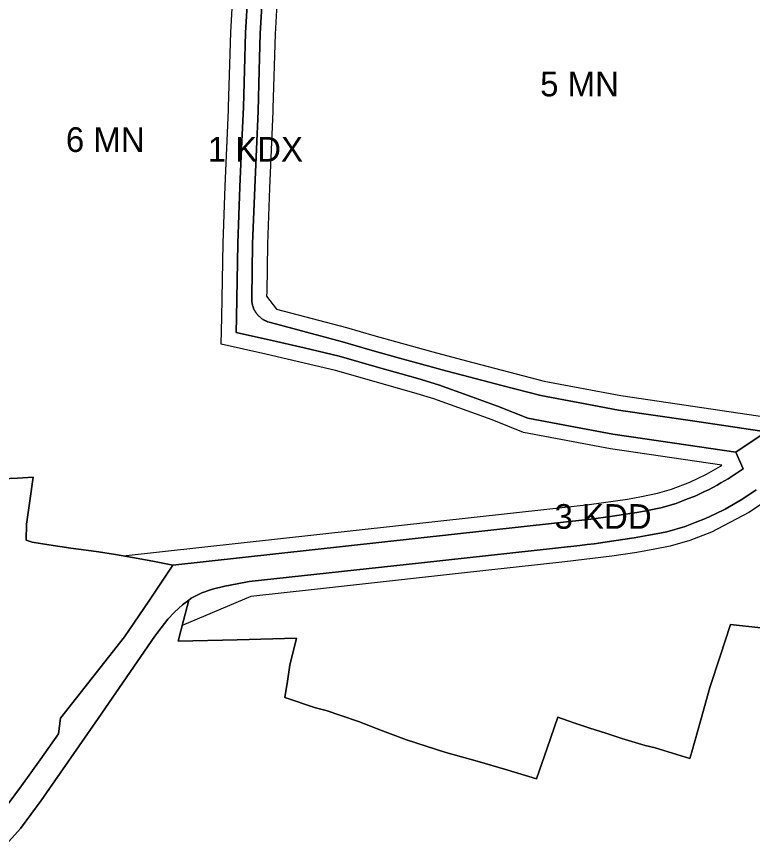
# Model space of a CAD drawing. Extents: x 7423432 to 7425824, y 5537848 to 5539677.
# Drawn here: x 7423719.6 to 7424018.1, y 5538438.2 to 5538772.8 of the extents above; entities that cross this region are included whole.
import ezdxf

# ---------------------------------------------------------------- set-up
doc = ezdxf.new("R2010")
doc.units = 0
for name, color, linetype in [('linie_rozgraniczajace', 7, 'Continuous'), ('linie_zabudowy_nieprzekraczalne', 7, 'Continuous'), ('oznaczenia_przeznaczen', 7, 'Continuous')]:
    doc.layers.add(name, color=color, linetype=linetype)

msp = doc.modelspace()

# ---------------------------------------------------------------- linework, layer by layer
at = {"layer": 'linie_rozgraniczajace'}
for points in [[(7423719.48, 5538874.86), (7423719.65, 5538874.75), (7423719.82, 5538874.64), (7423720, 5538874.54), (7423720.17, 5538874.44), (7423720.24, 5538874.4), (7423720.99, 5538874.02), (7423732.84, 5538868.82), (7423744.7, 5538863.63), (7423755.6, 5538859.21), (7423766.51, 5538854.8), (7423776.03, 5538851.5), (7423785.56, 5538848.2), (7423796.06, 5538844.9), (7423803.49, 5538842.6), (7423810.92, 5538840.3), (7423822.63, 5538838.5), (7423822.16, 5538830.31), (7423821.7, 5538822.11), (7423821.01, 5538809.88), (7423820.31, 5538797.65), (7423819.39, 5538781.73), (7423818.46, 5538765.81), (7423818.02, 5538750.81)], [(7423813.4, 5538782.03), (7423812.47, 5538766.07), (7423812.03, 5538751.03), (7423811.58, 5538735.98), (7423810.87, 5538719.18), (7423810.21, 5538703.69), (7423809.78, 5538692.21), (7423809.35, 5538680.73), (7423809.08, 5538665.72), (7423808.82, 5538650.7), (7423808.67, 5538644.66), (7423815.33, 5538643.18), (7423821.99, 5538641.71), (7423836.24, 5538638.37), (7423850.48, 5538635.03), (7423866.43, 5538630.49), (7423882.38, 5538625.95), (7423890.74, 5538623.35), (7423902.7, 5538619.07), (7423914.65, 5538614.79), (7423926.89, 5538609.87)], [(7423808.67, 5538644.66), (7423808.82, 5538650.7), (7423809.08, 5538665.72), (7423809.35, 5538680.73), (7423809.78, 5538692.21), (7423810.21, 5538703.69), (7423810.87, 5538719.18), (7423811.58, 5538735.98), (7423812.03, 5538751.03), (7423812.47, 5538766.07), (7423813.4, 5538782.03)], [(7423818.21, 5538650.91), (7423818.07, 5538651.05), (7423817.93, 5538651.18), (7423817.79, 5538651.32), (7423817.65, 5538651.46), (7423817.52, 5538651.61), (7423817.38, 5538651.75), (7423817.26, 5538651.9), (7423817.13, 5538652.06), (7423817.01, 5538652.21), (7423816.89, 5538652.37), (7423816.78, 5538652.53), (7423816.66, 5538652.69), (7423816.56, 5538652.85), (7423816.45, 5538653.02), (7423816.35, 5538653.19), (7423816.25, 5538653.36), (7423816.15, 5538653.53), (7423816.06, 5538653.71), (7423815.97, 5538653.88), (7423815.89, 5538654.06), (7423815.81, 5538654.24), (7423815.73, 5538654.42), (7423815.66, 5538654.6), (7423815.59, 5538654.79), (7423815.52, 5538654.97), (7423815.46, 5538655.16), (7423815.4, 5538655.35), (7423815.35, 5538655.54), (7423815.3, 5538655.73), (7423815.25, 5538655.92), (7423815.21, 5538656.11), (7423815.17, 5538656.3), (7423815.13, 5538656.5), (7423815.1, 5538656.69), (7423815.08, 5538656.89), (7423815.05, 5538657.08), (7423815.03, 5538657.28), (7423815.02, 5538657.47), (7423815.01, 5538657.67), (7423815, 5538657.87), (7423815, 5538658.06), (7423815, 5538658.26), (7423815, 5538658.46), (7423815.01, 5538658.65), (7423815.18, 5538669.61), (7423815.35, 5538680.57), (7423816.21, 5538703.45), (7423816.87, 5538718.94), (7423817.53, 5538734.42), (7423818.02, 5538750.81), (7423818.46, 5538765.81), (7423819.39, 5538781.73)], [(7423818.02, 5538750.81), (7423817.53, 5538734.42), (7423816.87, 5538718.94), (7423816.21, 5538703.45), (7423815.35, 5538680.57), (7423815.18, 5538669.61), (7423815.01, 5538658.65), (7423815, 5538658.46), (7423815, 5538658.26), (7423815, 5538658.06), (7423815, 5538657.87), (7423815.01, 5538657.67), (7423815.02, 5538657.47), (7423815.03, 5538657.28), (7423815.05, 5538657.08), (7423815.08, 5538656.89), (7423815.1, 5538656.69), (7423815.13, 5538656.5), (7423815.17, 5538656.3), (7423815.21, 5538656.11), (7423815.25, 5538655.92), (7423815.3, 5538655.73), (7423815.35, 5538655.54), (7423815.4, 5538655.35), (7423815.46, 5538655.16), (7423815.52, 5538654.97), (7423815.59, 5538654.79), (7423815.66, 5538654.6), (7423815.73, 5538654.42), (7423815.81, 5538654.24), (7423815.89, 5538654.06), (7423815.97, 5538653.88), (7423816.06, 5538653.71), (7423816.15, 5538653.53), (7423816.25, 5538653.36), (7423816.35, 5538653.19), (7423816.45, 5538653.02), (7423816.56, 5538652.85), (7423816.66, 5538652.69), (7423816.78, 5538652.53), (7423816.89, 5538652.37), (7423817.01, 5538652.21), (7423817.13, 5538652.06), (7423817.26, 5538651.9), (7423817.38, 5538651.75), (7423817.52, 5538651.61), (7423817.65, 5538651.46), (7423817.79, 5538651.32), (7423817.93, 5538651.18), (7423818.07, 5538651.05), (7423818.21, 5538650.91), (7423818.36, 5538650.78), (7423818.51, 5538650.66), (7423818.66, 5538650.53), (7423818.82, 5538650.41), (7423818.98, 5538650.3), (7423819.14, 5538650.18), (7423819.3, 5538650.07), (7423819.47, 5538649.96), (7423819.63, 5538649.86), (7423819.8, 5538649.76), (7423819.97, 5538649.66), (7423820.15, 5538649.57), (7423820.32, 5538649.48), (7423820.5, 5538649.39), (7423820.68, 5538649.3), (7423820.86, 5538649.23), (7423821.04, 5538649.15), (7423821.22, 5538649.08), (7423821.4, 5538649.01), (7423821.57, 5538648.95), (7423822.59, 5538648.65), (7423837.22, 5538644.76), (7423851.85, 5538640.87), (7423862.87, 5538637.61), (7423874.84, 5538634.28), (7423886.82, 5538630.96), (7423893.65, 5538629.12), (7423900.48, 5538627.29), (7423916.36, 5538623.16), (7423932.25, 5538619.04), (7423947.99, 5538616.1), (7423963.72, 5538613.17), (7423993.67, 5538608.75), (7424023.61, 5538604.33), (7424011.34, 5538596.04), (7423986.4, 5538599.72), (7423961.45, 5538603.39), (7423944.17, 5538606.63), (7423926.89, 5538609.87), (7423914.65, 5538614.79), (7423902.7, 5538619.07), (7423890.74, 5538623.35), (7423882.38, 5538625.95), (7423866.43, 5538630.49), (7423850.48, 5538635.03), (7423836.24, 5538638.37), (7423821.99, 5538641.71), (7423815.33, 5538643.18), (7423808.67, 5538644.66)], [(7424023.61, 5538604.33), (7423993.67, 5538608.75), (7423963.72, 5538613.17), (7423947.99, 5538616.1), (7423932.25, 5538619.04), (7423916.36, 5538623.16), (7423900.48, 5538627.29), (7423893.65, 5538629.12), (7423886.82, 5538630.96), (7423874.84, 5538634.28), (7423862.87, 5538637.61), (7423851.85, 5538640.87), (7423837.22, 5538644.76), (7423822.59, 5538648.65), (7423821.57, 5538648.95), (7423821.4, 5538649.01), (7423821.22, 5538649.08), (7423821.04, 5538649.15), (7423820.86, 5538649.23), (7423820.68, 5538649.3), (7423820.5, 5538649.39), (7423820.32, 5538649.48), (7423820.15, 5538649.57), (7423819.97, 5538649.66), (7423819.8, 5538649.76), (7423819.63, 5538649.86), (7423819.47, 5538649.96), (7423819.3, 5538650.07), (7423819.14, 5538650.18), (7423818.98, 5538650.3), (7423818.82, 5538650.41), (7423818.66, 5538650.53), (7423818.51, 5538650.66), (7423818.36, 5538650.78), (7423818.21, 5538650.91)], [(7423926.89, 5538609.87), (7423944.17, 5538606.63), (7423961.45, 5538603.39), (7423986.4, 5538599.72), (7424011.34, 5538596.04), (7424014.31, 5538589.31), (7424008.21, 5538585.35), (7424005.23, 5538583.61), (7424003.7, 5538582.71), (7424002.26, 5538581.87), (7424000.17, 5538580.85), (7423998.64, 5538580.11), (7423995.01, 5538578.36), (7423991.07, 5538576.84), (7423987.13, 5538575.33), (7423980.93, 5538573.59), (7423974.11, 5538572.23), (7423971.21, 5538571.7), (7423968.31, 5538571.17), (7423960.41, 5538570.02), (7423952.52, 5538568.87), (7423867.75, 5538559.56), (7423782.99, 5538550.25), (7423774.84, 5538551.85), (7423766.69, 5538553.44), (7423759.79, 5538554.57), (7423752.89, 5538555.7), (7423747.79, 5538556.32), (7423741.65, 5538557.21), (7423732.65, 5538558.59), (7423725.99, 5538559.67), (7423723.52, 5538560.35), (7423723.71, 5538566.88), (7423725.01, 5538576.42), (7423726.32, 5538585.95), (7423720.05, 5538585.62), (7423713.79, 5538585.28)], [(7423713.46, 5538449.88), (7423721.65, 5538460.83), (7423729.13, 5538471.33), (7423736.62, 5538481.83), (7423737.03, 5538485.04), (7423737.45, 5538488.25), (7423750.45, 5538504.71), (7423763.45, 5538521.17), (7423773.22, 5538535.71), (7423782.99, 5538550.25), (7423867.75, 5538559.56), (7423952.52, 5538568.87), (7423960.41, 5538570.02), (7423968.31, 5538571.17), (7423971.21, 5538571.7), (7423974.11, 5538572.23), (7423980.93, 5538573.59), (7423987.13, 5538575.33), (7423991.07, 5538576.84), (7423995.01, 5538578.36), (7423998.64, 5538580.11), (7424000.17, 5538580.85), (7424002.26, 5538581.87), (7424003.7, 5538582.71), (7424005.23, 5538583.61), (7424008.21, 5538585.35), (7424014.31, 5538589.31), (7424011.34, 5538596.04), (7424023.61, 5538604.33)], [(7423713.79, 5538585.28), (7423720.05, 5538585.62), (7423726.32, 5538585.95), (7423725.01, 5538576.42), (7423723.71, 5538566.88), (7423723.52, 5538560.35), (7423725.99, 5538559.67), (7423732.65, 5538558.59), (7423741.65, 5538557.21), (7423747.79, 5538556.32), (7423752.89, 5538555.7), (7423759.79, 5538554.57), (7423766.69, 5538553.44), (7423774.84, 5538551.85), (7423782.99, 5538550.25), (7423773.22, 5538535.71), (7423763.45, 5538521.17), (7423750.45, 5538504.71), (7423737.45, 5538488.25), (7423737.03, 5538485.04), (7423736.62, 5538481.83), (7423729.13, 5538471.33), (7423721.65, 5538460.83), (7423713.46, 5538449.88)], [(7424019.55, 5538580.78), (7424016.5, 5538578.81), (7424013.46, 5538576.83), (7424010.21, 5538574.93), (7424006.97, 5538573.04), (7424002.98, 5538571.11), (7423998.98, 5538569.17), (7423994.85, 5538567.59), (7423990.72, 5538566), (7423983.26, 5538563.86), (7423981.1, 5538563.43), (7423975.99, 5538562.41), (7423970.11, 5538561.33), (7423961.77, 5538560.11), (7423953.78, 5538558.95), (7423950.99, 5538558.65), (7423948.01, 5538558.32), (7423883.89, 5538551.28), (7423814.01, 5538543.6), (7423809.08, 5538542.71), (7423804.14, 5538541.8), (7423799.04, 5538540.51), (7423794.69, 5538539.08), (7423790.49, 5538536.84), (7423789.53, 5538536.15), (7423786.89, 5538534.24), (7423783.62, 5538531.26), (7423780.94, 5538528.38), (7423778.3, 5538524.93), (7423775.65, 5538521.49), (7423752.65, 5538488.16), (7423729.66, 5538454.84), (7423725.43, 5538449.19), (7423721.2, 5538443.54), (7423716.53, 5538438.23)], [(7423785.09, 5538519.43), (7423787.31, 5538527.79), (7423789.53, 5538536.15), (7423790.49, 5538536.84), (7423794.69, 5538539.08), (7423799.04, 5538540.51), (7423804.14, 5538541.8), (7423809.08, 5538542.71), (7423814.01, 5538543.6), (7423883.89, 5538551.28), (7423948.01, 5538558.32), (7423950.99, 5538558.65), (7423953.78, 5538558.95), (7423961.77, 5538560.11), (7423970.11, 5538561.33), (7423975.99, 5538562.41), (7423981.1, 5538563.43), (7423983.26, 5538563.86), (7423990.72, 5538566), (7423994.85, 5538567.59), (7423998.98, 5538569.17), (7424002.98, 5538571.11), (7424006.97, 5538573.04), (7424010.21, 5538574.93), (7424013.46, 5538576.83), (7424016.5, 5538578.81), (7424019.55, 5538580.78)], [(7423716.53, 5538438.23), (7423721.2, 5538443.54), (7423725.43, 5538449.19), (7423729.66, 5538454.84), (7423752.65, 5538488.16), (7423775.65, 5538521.49), (7423778.3, 5538524.93), (7423780.94, 5538528.38), (7423783.62, 5538531.26), (7423786.89, 5538534.24), (7423789.53, 5538536.15), (7423787.31, 5538527.79), (7423785.09, 5538519.43), (7423809.14, 5538520.06), (7423833.19, 5538520.69), (7423830.46, 5538509.75), (7423829.46, 5538503.2), (7423828.46, 5538496.66), (7423840.84, 5538492.37), (7423845.16, 5538491.34), (7423851.14, 5538489.28), (7423858.3, 5538486.83), (7423868.05, 5538483.17), (7423877.8, 5538479.51), (7423885.76, 5538476.92), (7423893.72, 5538474.32), (7423900.03, 5538472.56), (7423906.35, 5538470.8), (7423918.39, 5538467.25), (7423930.43, 5538463.7), (7423934.74, 5538476.14), (7423939.05, 5538488.59), (7423945.58, 5538486.4), (7423952.11, 5538484.21), (7423958.56, 5538482.09), (7423965, 5538479.96), (7423974.54, 5538477.13), (7423978.6, 5538476.27), (7423992.65, 5538471.92), (7423993.41, 5538474.59), (7423997.11, 5538487.6), (7424000.81, 5538500.61), (7424004.96, 5538513.44), (7424009.11, 5538526.28), (7424021.37, 5538524.88)], [(7424021.37, 5538524.88), (7424009.11, 5538526.28), (7424004.96, 5538513.44), (7424000.81, 5538500.61), (7423997.11, 5538487.6), (7423993.41, 5538474.59), (7423992.65, 5538471.92), (7423978.6, 5538476.27), (7423974.54, 5538477.13), (7423965, 5538479.96), (7423958.56, 5538482.09), (7423952.11, 5538484.21), (7423945.58, 5538486.4), (7423939.05, 5538488.59), (7423934.74, 5538476.14), (7423930.43, 5538463.7), (7423918.39, 5538467.25), (7423906.35, 5538470.8), (7423900.03, 5538472.56), (7423893.72, 5538474.32), (7423885.76, 5538476.92), (7423877.8, 5538479.51), (7423868.05, 5538483.17), (7423858.3, 5538486.83), (7423851.14, 5538489.28), (7423845.16, 5538491.34), (7423840.84, 5538492.37), (7423828.46, 5538496.66), (7423829.46, 5538503.2), (7423830.46, 5538509.75), (7423833.19, 5538520.69), (7423809.14, 5538520.06), (7423785.09, 5538519.43)]]:
    msp.add_lwpolyline(points, dxfattribs=at)
at = {"layer": 'linie_zabudowy_nieprzekraczalne'}
for points in [[(7423762.83, 5538554.07), (7423951.76, 5538574.83), (7423967.34, 5538577.09), (7423972.99, 5538578.12), (7423979.53, 5538579.43), (7423985.24, 5538581.03), (7423992.62, 5538583.87), (7423999.44, 5538587.16), (7424005.06, 5538590.45), (7424005.62, 5538590.82), (7423960.46, 5538597.47), (7423925.2, 5538604.08), (7423912.52, 5538609.18), (7423888.83, 5538617.66), (7423880.66, 5538620.2), (7423848.98, 5538629.22), (7423820.66, 5538635.86), (7423802.55, 5538639.87), (7423802.82, 5538650.83), (7423803.35, 5538680.9), (7423804.22, 5538703.93), (7423805.54, 5538734.9), (7423805.58, 5538736.18), (7423806.47, 5538766.33), (7423808.33, 5538798.34)], [(7423826.3, 5538797.3), (7423824.46, 5538765.54), (7423823.57, 5538735.61), (7423823.52, 5538734.19), (7423822.2, 5538703.21), (7423821.35, 5538680.4), (7423821.04, 5538661.05), (7423820.97, 5538659.35), (7423825.08, 5538654.12), (7423853.47, 5538646.65), (7423864.52, 5538643.38), (7423888.4, 5538636.75), (7423902.01, 5538633.09), (7423933.56, 5538624.9), (7423964.71, 5538619.08), (7424023.99, 5538610.34)], [(7424030.59, 5538581.01), (7424016.53, 5538571.67), (7424001.47, 5538563.7), (7423992.63, 5538560.3), (7423984.67, 5538558.03), (7423978.43, 5538556.78), (7423971.09, 5538555.41), (7423961.07, 5538553.95), (7423941.98, 5538551.62), (7423899.98, 5538547.01), (7423840.44, 5538540.4), (7423814.64, 5538537.63), (7423814.64, 5538537.63), (7423814.64, 5538537.63), (7423814.64, 5538537.63), (7423814.64, 5538537.63), (7423786.8, 5538525.87), (7423786.8, 5538525.87), (7423786.8, 5538525.87), (7423786.8, 5538525.87)]]:
    msp.add_lwpolyline(points, dxfattribs=at)

# ---------------------------------------------------------------- texts
at = {"layer": 'oznaczenia_przeznaczen'}
for s, p in [('5 MN', (7423931.94, 5538740.37)), ('6 MN', (7423739.62, 5538717.83)), ('1 KDX', (7423797.13, 5538713.93)), ('3 KDD', (7423937.76, 5538565.02))]:
    msp.add_text(s, height=10, dxfattribs=at).set_placement(p)

doc.saveas('drawing.dxf')
